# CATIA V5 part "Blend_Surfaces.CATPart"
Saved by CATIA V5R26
Part number: Blend_Surfaces
Bounding box of the stored display mesh (mm): x -221.31 to 305.063, y -86.794 to 141.022, z -45.705 to 27.074
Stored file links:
  D:\LinkedIn Learning\NURBS\CATIA\Class Parts\Blend_Surfaces.CATPart
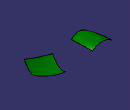
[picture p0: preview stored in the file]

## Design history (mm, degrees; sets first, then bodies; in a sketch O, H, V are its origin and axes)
AxisSystem1: origin (0, 0, 0), X (1, 0, 0), Y (0, 1, 0), Z (0, 0, 1)
Set1
  DatumSurface1
  DatumSurface2
Body1 (main body)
